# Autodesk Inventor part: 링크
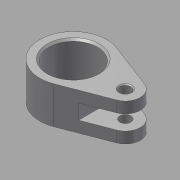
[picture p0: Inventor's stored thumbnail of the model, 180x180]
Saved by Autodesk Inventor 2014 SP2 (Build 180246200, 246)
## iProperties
Created: 2015-12
Part Number: 링크
Material: 강철, 연강
Document SubType Name: Modeling
Designer: mduedu
Density: 7.86 g/cm^3
Appearance: 강철
Author: mduedu
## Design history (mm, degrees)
sketch "스케치1"
  geometry: L1 (6.429, -16.813)-(30.857, -7.472); L2 (6.429, 16.813)-(30.857, 7.472); A1 r 18 centre (0, 0) between (6.429, 16.813) and (6.429, -16.813); A2 r 8 centre (28, 0) between (30.857, -7.472) and (30.857, 7.472); 1 further point
  constraints: 4 end point, 4 point on circle, 4 tangent, 2 centre point, 1 coincident, 1 horizontal alignment
  dimensions: "d0" = 18 radius of A1; "d1" = 8 radius of A2; "d2" = 28 distance of A2.centre point (0, 0)
extrude "돌출1" new body sketch "스케치1" stored distance "d3" = 20; taper "d4" = 0 deg
sketch "스케치2"
  geometry: L1 (6.429, 16.813)-(30.857, 7.472) reference; L2 (30.857, -7.472)-(6.429, -16.813) reference; L3 (16, 13.153)-(16, -13.153); A1 r 8 centre (28, 0) between (30.857, -7.472) and (30.857, 7.472) reference; 1 further point
  constraints: 2 end point, 2 point on line, 1 vertical
  dimensions: "d5" = 20 dimension on A1 L3
extrude "돌출2" cut sketch "스케치2" stored distance "d6" = 8; taper "d7" = 0 deg
hole "구멍1" diameter "d10" = 26; stored, may be unused: countersink angle "d14" = 90 deg, drill point angle "d16" = 118 deg; dims "d8" = 10, "d9" = 10, "d11" = 6, "d12" = 4, "d13" = 2, "d15" = 8
hole "구멍2" diameter "d19" = 6; stored, may be unused: countersink angle "d23" = 90 deg, drill point angle "d25" = 118 deg; dims "d20" = 6, "d21" = 4, "d22" = 2, "d24" = 8, "d32" = 10, "d33" = 10
chamfer "모따기1" distance "d26" = 1; stored, may be unused: second distance "d27" = 2, angle "d28" = 45 deg
chamfer "모따기2" distance "d29" = 0.5; stored, may be unused: second distance "d30" = 2, angle "d31" = 45 deg
node "솔리드1"
